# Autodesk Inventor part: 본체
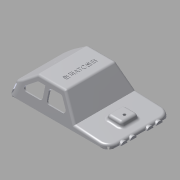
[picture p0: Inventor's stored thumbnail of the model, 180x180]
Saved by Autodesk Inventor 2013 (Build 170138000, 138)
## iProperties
Created: 2015-05
Part Number: 본체
Material: ABS 플라스틱
Document SubType Name: Modeling
Designer: WINDOWS7
Density: 1.06 g/cm^3
Mass: 31.6438 g
Surface Area: 310.19 cm^2
Volume: 29.8527 cm^3
Author: WINDOWS7
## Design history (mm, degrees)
sketch "스케치2"
  geometry: L1 (-58.819, 3.58)-(63.181, 3.58); L2 (-58.819, 3.58)-(-63.995, 22.898); L3 (-58.819, 3.58)-(-38.819, 3.58); L4 (-58.819, 3.58)-(-58.819, 23); L5 (-58.819, 3.58)-(-58.623, 7.814); L6 (-58.623, 7.814)-(-16.819, 10.005); L7 (-16.819, 3.58)-(-16.819, 52); L8 (-16.819, 10.005)-(-34.026, 34.58); L9 (-16.819, 10.005)-(13.181, 10.005); L10 (-16.819, 10.005)-(0.388, 34.58); L11 (33.181, 3.58)-(33.181, 49.685); L12 (0.388, 34.58)-(33.181, 34.58); L13 (63.181, 3.58)-(60.334, 14.205); L14 (63.181, 3.58)-(74.181, 3.58); L15 (60.334, 14.205)-(33.181, 34.58); 2 further points
  constraints: 30 end point, 4 horizontal, 4 point on line, 3 equal length, 3 perpendicular, 2 symmetric about line, 1 parallel
  dimensions: "d3" = 122 distance of L1.end L1.start; "d7" = 20 distance of L1.start L2.end; "d8" = 105 deg angle of L3 L2; "d10" = 3 deg angle of L1 L6; "d11" = 58.92148 distance from line of L5 point (0, 0); "d16" = 42 distance from line of L1.start L7; "d17" = 30 distance of L6.end L8.end; "d18" = 125 deg angle of L9 L8; "d19" = 30 distance from line of L1.end L11; "d20" = 11 distance of L1.end L13.end; "d21" = 105 deg angle of L14 L13 (derived); "d23" = 128 deg angle of L6 L10; "d24" = 4.27949 distance from line of point (-53.643, 22.898) L5; "d73" = 31 distance between parallel lines of L1 L12; "d76" = 3.5798 vertical distance of L1.start point (0, 0)
extrude "돌출1" new body sketch "스케치2" distance "d25" = 76; taper "d26" = 0 deg
sketch "스케치3"
  geometry: L1 (0, 0)-(122, 0) reference; L2 (122, 0)-(122, 76) reference; L3 (0, 76)-(122, 76) reference; L4 (0, 0)-(0, 76) reference; L5 (1, 75)-(121, 75); L6 (121, 75)-(121, 1); L7 (121, 1)-(1, 1); L8 (1, 1)-(1, 75); 1 further point
  constraints: 8 end point, 2 parallel, 1 horizontal, 1 perpendicular
  dimensions: "d28" = 120 distance between parallel lines of L6 L8; "d30" = 74 distance between parallel lines of L7 L5; "d31" = 1 distance between parallel lines of L1 L7; "d32" = 1 distance between parallel lines of L4 L8
extrude "돌출2" cut sketch "스케치3" distance "d33" = 1; taper "d34" = 0 deg
node "작업 평면1"
sketch "스케치5"
  geometry: L1 (62.913, 4.58)-(-58.773, 4.58) reference; L2 (-58.623, 7.814)-(-58.773, 4.58) reference; L3 (-16.819, 10.005)-(-58.623, 7.814) reference; L4 (0.388, 34.58)-(-16.819, 10.005) reference; L5 (33.181, 34.58)-(0.388, 34.58) reference; L6 (60.334, 14.205)-(33.181, 34.58) reference; L7 (62.913, 4.58)-(60.334, 14.205) reference; L8 (-47.623, 8.391)-(-45.774, 14.439); L9 (-45.774, 14.439)-(-29.746, 14.439); L10 (-29.746, 14.439)-(-27.623, 9.439); L11 (-15.901, 8.051)-(-56.709, 5.912) reference; 1 further point
  constraints: 6 end point, 2 point on line, 1 parallel
  dimensions: "d35" = 70 deg angle of L3 L8; "d36" = 70 deg angle of L3 L10; "d37" = 11 horizontal distance of L2.start L8.start; "d38" = 20 horizontal distance of L10.end L8.start; "d39" = 5 distance from line of L10.end L9
extrude "돌출3" join sketch "스케치5" stored distance "d40" = 20; taper "d41" = 0 deg
node "작업 평면2"
sketch "스케치7"
  geometry: L1 (0, 9.625)-(0, 30) reference; L2 (0, 30)-(76, 30) reference; L3 (76, 9.625)-(76, 30) reference; L4 (0, 9.625)-(76, 9.625) reference; L5 (76, 0)-(0, 0) reference; L6 (0, 0)-(0, 9.625) reference; L7 (0, 9.625)-(76, 9.625) reference; L8 (76, 0)-(76, 9.625) reference; L9 (76, 0)-(67.962, 30); L10 (0, 0)-(8.038, 30); L11 (0, 0)-(0, 30); L12 (8.038, 30)-(0, 30); L13 (67.962, 30)-(76, 30); L14 (76, 0)-(76, 30); 1 further point
  constraints: 14 end point, 2 point on line, 1 collinear
  dimensions: "d44" = 105 deg angle of L5 L9; "d45" = 105 deg angle of L5 L10
extrude "돌출4" cut sketch "스케치7" distance "d46" = 122; taper "d47" = 0 deg
feature "쉘2" dims "d48" = 2
sketch "스케치8"
  geometry: L1 (79.732, -5.617)-(62.525, -31.058) reference; L2 (62.525, -31.058)-(29.732, -31.058) reference; L3 (70.015, -11.058)-(59.87, -26.058); L4 (45.015, -11.058)-(45.015, -26.058); L5 (29.732, -31.058)-(2.579, -9.965); L6 (31.446, -26.058)-(12.137, -11.058); L7 (12.137, -11.058)-(40.137, -11.058); L8 (40.137, -11.058)-(40.137, -26.058); L9 (40.137, -26.058)-(31.446, -26.058); L10 (70.015, -11.058)-(45.015, -11.058); L11 (45.015, -26.058)-(59.87, -26.058); 1 further point
  constraints: 18 end point, 3 horizontal alignment, 3 parallel, 2 perpendicular, 2 vertical alignment
  dimensions: "d59" = 5 distance between parallel lines of L1 L3; "d65" = 25 distance from line of L3.start L4; "d67" = 5 distance between parallel lines of L5 L6; "d68" = 28 distance of L6.end L7.end; "d69" = 5 distance between parallel lines of L11 L2; "d70" = 15 distance between parallel lines of L10 L11; "d71" = 5 distance between parallel lines of L2 L9; "d72" = 15 distance between parallel lines of L7 L9
extrude "돌출5" cut sketch "스케치8" distance "d74" = 5; taper "d75" = 0 deg
node "작업 평면3"
sketch "스케치9"
  geometry: L1 (-3.238, 0.867)-(-3.238, 75.133) reference; L2 (0.955, 38)-(-91.897, 38); L3 (0.955, 75)-(0.955, 1) reference; L4 (0.955, 75)-(-0.044, 75) reference; L5 (-0.044, 75)-(-0.044, 1) reference; L6 (0.955, 1)-(-0.044, 1) reference; L7 (0, 13.116)-(0, 20.884); L8 (0, 24.116)-(0, 31.884); L9 (0, 44.116)-(0, 51.884); L10 (0, 55.116)-(0, 62.884); A1 r 4 centre (0.955, 28) between (0, 31.884) and (0, 24.116); A2 r 4 centre (0.955, 17) between (0, 20.884) and (0, 13.116); A3 r 4 centre (0.955, 48) between (0, 51.884) and (0, 44.116); A4 r 4 centre (0.955, 59) between (0, 62.884) and (0, 55.116); 3 further points
  constraints: 10 end point, 8 point on circle, 4 centre point, 4 point on line, 2 vertical, 1 collinear, 1 midpoint, 1 parallel, 1 perpendicular, 9 other
  dimensions: "d79" = 8 diameter of A1; "d80" = 8 diameter of A2; "d85" = 11 distance of A4.centre A3.centre; "d86" = 11 distance of A1.centre A2.centre; "d87" = 10 distance of L2.start A3.centre; "d88" = 10 distance of L2.start A1.centre; "d89" = 4 radius of A3; "d90" = 4 radius of A4
extrude "돌출6" join sketch "스케치9" distance "d91" = 2; taper "d92" = 0 deg
sketch "스케치11"
  geometry: L1 (120, 74)-(0, 74) reference; L2 (120.732, 75)-(120.732, -1) reference; L3 (57.819, -6)-(57.819, 86); L4 (148, 37)-(-11, 37); C1 r 3 at (97.819, 37); C2 r 3 at (17.819, 37); C3 r 3 at (57.819, 15); C4 r 3 at (57.819, 59); 2 further points
  constraints: 6 point on line, 4 centre point, 4 end point, 2 perpendicular, 1 midpoint
  dimensions: "d97" = 6 diameter of C1; "d99" = 40 distance from line of L3 C1.centre; "d100" = 40 distance from line of L3 C2.centre; "d101" = 6 diameter of C2; "d102" = 6 diameter of C3; "d103" = 6 diameter of C4; "d104" = 22 distance from line of L4 C3.centre; "d105" = 22 distance from line of L4 C4.centre
extrude "돌출8" join sketch "스케치11" distance "d106" = 10; taper "d107" = 0 deg
extrude "돌출9" join sketch "스케치11" distance "d108" = 24; taper "d109" = 0 deg
node "작업 평면5"
sketch "스케치12"
  geometry: L1 (3, 0)-(-3, 0) reference; L2 (-2.072, 24)-(-2.072, 24) reference; L3 (-2.072, 24)-(-2.072, 24) reference; L4 (3, 0)-(3, 24) reference; L5 (-3, 0)-(-3, 22.674) reference; L6 (3, 24)-(-2.072, 24) reference; L7 (62.181, 0)-(-57.819, 0) reference; L8 (-3, 2)-(-5, 2); L9 (3, 2)-(5, 2); L10 (5, 2)-(8.522, 24); L11 (8.522, 24)-(3, 24); L12 (1.429, 29)-(-15.74, 4.479) reference; L13 (-5, 2)-(-7.673, 16); L14 (-7.673, 16)-(-3, 16); L15 (0, 0)-(0, 0); L16 (0, 0)-(0, 14); 1 further point
  constraints: 16 end point, 5 point on line, 3 perpendicular, 2 midpoint, 2 parallel, 1 collinear
  dimensions: "d114" = 5 horizontal distance of L15.start L8.end; "d116" = 5 horizontal distance of L15.start L9.end
extrude "돌출10" join sketch "스케치12" stored distance "d117" = 4; taper "d118" = 0 deg
node "작업 평면6"
sketch "스케치13"
  geometry: L1 (-3, 2)-(-4, 2); L2 (-4, 2)-(-5.076, 6.303); L3 (3, 2)-(4, 2); L4 (4, 2)-(6.951, 8.859); L5 (3, 0)-(-3, 0) reference; L6 (3, 8.859)-(-3, 8.859) reference; L7 (3, 0)-(3, 8.859) reference; L8 (-3, 0)-(-3, 8.859) reference; L9 (3, 8.859)-(6.951, 8.859); L10 (-6.12, 2.887)-(-4.294, 8.859) reference; L11 (-5.076, 6.303)-(-3, 6.303); L12 (0, 0)-(0, 8.859); L13 (83, 0)-(77, 0) reference; L14 (79.177, 24)-(79.177, 24) reference; L15 (79.177, 24)-(79.177, 24) reference; L16 (77, 0)-(77, 24) reference; L17 (83, 0)-(83, 21.132) reference; L18 (98.581, 9.44)-(72.514, 29) reference; L19 (77, 2)-(75, 2); L20 (75, 2)-(70, 24); L21 (70, 24)-(77, 24); L22 (83, 2)-(85, 2); L23 (85, 2)-(88, 18); L24 (88, 18)-(83, 18); L25 (80, 0)-(80, 14.557); L26 (-3, 6.303)-(-3, 2); L27 (83, 18)-(83, 2); L28 (77, 24)-(77, 2); 4 further points
  constraints: 34 end point, 8 point on line, 5 perpendicular, 4 collinear, 3 midpoint, 2 horizontal, 2 vertical alignment, 1 horizontal alignment, 1 parallel, 2 other
  dimensions: "d119" = 4 horizontal distance of L12.start L1.end; "d120" = 4 horizontal distance of L12.start L3.end; "d121" = 4.30315 distance between parallel lines of L1 L11; "d124" = 5 distance from line of L25 L22.end; "d125" = 5 distance from line of L25 L19.end; "d126" = 16 distance between parallel lines of L22 L24
  node "투영된 루프7"
  node "투영된 루프8"
extrude "돌출11" join sketch "스케치13" stored distance "d127" = 4; taper "d128" = 0 deg
extrude "돌출12" join sketch "스케치13" stored distance "d129" = 4; taper "d130" = 0 deg
extrude "돌출13" join sketch "스케치13" stored distance "d131" = 4; taper "d132" = 0 deg
node "작업 평면7"
sketch "스케치14"
  geometry: L1 (3, 0)-(-3, 0) reference; L2 (-2.072, 24)-(-2.072, 24) reference; L3 (-2.072, 24)-(-2.072, 24) reference; L4 (3, 0)-(3, 24) reference; L5 (-3, 0)-(-3, 22.674) reference; L6 (62.181, 0)-(-57.819, 0) reference; L7 (3, 24)-(-2.072, 24) reference; L8 (-3, 2)-(-5, 2); L9 (-5, 2)-(-7, 16); L10 (-7, 16)-(-3, 16); L11 (3, 2)-(5, 2); L12 (5, 2)-(10, 24); L13 (10, 24)-(3, 24); L14 (3, 24)-(3, 2); L15 (-3, 16)-(-3, 2); L16 (0, 0)-(0, 13.594); 2 further points
  constraints: 18 end point, 5 point on line, 4 parallel, 2 collinear, 1 midpoint, 1 perpendicular
  dimensions: "d133" = 5 distance from line of L16 L11.end; "d135" = 5 distance from line of L16 L8.end; "d136" = 14 distance between parallel lines of L8 L10; "d137" = 22 distance between parallel lines of L11 L13
extrude "돌출14" join sketch "스케치14" stored distance "d138" = 4; taper "d139" = 0 deg
fillet "모깎기1" dims "d140" = 12
fillet "모깎기2" dims "d141" = 3
fillet "모깎기3" dims "d142" = 3
fillet "모깎기4" dims "d143" = 3
fillet "모깎기5" dims "d144" = 3
sketch "스케치15"
  geometry: L1 (0, 0)-(0, 55.319) reference; L2 (30.231, 55.319)-(30.231, 0) reference; L3 (-30.732, 54.068)-(-30.732, 1.251) reference; L4 (19.268, 8.241)-(19.268, 47.078); L5 (16.422, 27.66)-(22.114, 27.66); L6 (0, 27.66)-(30.231, 27.66); 4 further points
  constraints: 6 end point, 4 midpoint, 1 point on line, 1 other
  dimensions: "d145" = 50 distance from line of point (19.268, 27.66) L3
extrude "돌출15" join sketch "스케치15" distance "d146" = 0.5; taper "d147" = 0 deg
hole "구멍1" diameter "d150" = 3.242; stored, may be unused: countersink angle "d154" = 90 deg, drill point angle "d156" = 118 deg; dims "d148" = 10, "d149" = 10, "d151" = 9, "d152" = 4, "d153" = 2, "d155" = 11
hole "구멍2" diameter "d159" = 3.242; stored, may be unused: countersink angle "d163" = 90 deg, drill point angle "d165" = 118 deg; dims "d157" = 10, "d158" = 10, "d160" = 9, "d161" = 4, "d162" = 2, "d164" = 11
hole "구멍3" diameter "d168" = 3.242; stored, may be unused: countersink angle "d172" = 90 deg, drill point angle "d174" = 118 deg; dims "d166" = 10, "d167" = 10, "d169" = 9, "d170" = 4, "d171" = 2, "d173" = 11
hole "구멍4" diameter "d177" = 3.242; stored, may be unused: countersink angle "d181" = 90 deg, drill point angle "d183" = 118 deg; dims "d175" = 10, "d176" = 10, "d178" = 9, "d179" = 4, "d180" = 2, "d182" = 11
node "솔리드1"
mirror "대칭1"
node "투영된 루프1"
node "투영된 루프3"
node "투영된 루프4"
node "투영된 루프5"
node "투영된 루프6"
node "투영된 루프9"
other parameters: "d60" = 5, "d61" = 15, "d81" = 8, "d82" = 8
